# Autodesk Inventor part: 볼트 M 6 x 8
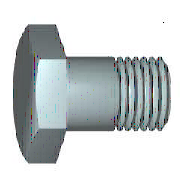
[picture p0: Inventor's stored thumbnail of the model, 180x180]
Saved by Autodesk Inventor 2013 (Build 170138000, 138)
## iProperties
Created: 2012-02
Part Number: 볼트 M 6 x 8
Material: 강철, 연강
Description: 6각 머리 볼트 및 6각 머리 나사
Document SubType Name: Modeling
Standard: KS B 1002
Designer: mduedu
Standards Organization: KS
Language: ko-KR
Size Designation: C  M 6 x 12
Categories: <MemberInstance><Categories><Category DisplayName="조임쇠" InternalName="e4da775c-781d-43d5-af7c-5136215cf5a6" Mnemonic="FSTN"><Category DisplayName="볼트" InternalN
Density: 1 g/cm^3
IsCustomPart: 1
Author: mduedu
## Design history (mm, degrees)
sketch "스케치1"
  geometry: L1 (0, 3)-(8, 3); L2 (8, 3)-(8, 0); L3 (8, 0)-(0, 0); L4 (-2.4, 0)-(14.4, 0) reference; L5 (0, -0.6)-(0, 3.6) reference; L6 (0, 3)-(0, 0)
  constraints: 8 end point, 3 point on line, 1 collinear
  dimensions: "d2" = 6 diameter of L1 L3 (= GD); "d59" = 8 distance between parallel lines of L2 L5 (= NLG)
revolve "본체" sketch "스케치1" stored, may be unused: angle "d12" = 90 deg
sketch "스케치2"
  geometry: L1 (0, 5.774)-(5, 2.887); L2 (5, 2.887)-(5, -2.887); L3 (5, -2.887)-(0, -5.774); L4 (0, -5.774)-(-5, -2.887); L5 (-5, -2.887)-(-5, 2.887); L6 (-5, 2.887)-(0, 5.774); L7 (-7, 0)-(7, 0) reference; L8 (0, 8.083)-(0, -8.083) reference; 2 further points
  constraints: 12 end point, 2 midpoint, 1 coincident, 1 vertical, 11 other
  dimensions: "d11" = 10 distance between parallel lines of L5 L2 (= SW)
extrude "머리" join sketch "스케치2" distance "d3" = 4 (= KOH); taper "d4" = 0 deg
revolve "모따기1" stored, may be unused: angle "d21" = 90 deg
workplane "Work Plane1"
body "Solid1"
feature "스레드" dims "d15" = 9 (= GEL), "d16" = 0
chamfer "모따기2" distance "d6" = 0.61345 (= -0.5 x SPD + 0.5 x GD); stored, may be unused: second distance "d7" = 0.61355 (computed from GUL), angle "d55" = 45 deg
sketch "스케치4"
  geometry: L1 (-3.423, 6)-(-4, 5); L2 (-1.1, 0)-(-0.234, 0); L3 (-4.753, 0)-(0.519, 0) reference; L4 (-4, 6)-(-3.423, 6); L5 (-4, 5)-(-4, 6); L6 (0, 7.2)-(0, -1.2) reference
  constraints: 8 end point, 1 parallel, 1 perpendicular, 1 point on line
  dimensions: "d65" = 10 diameter of L1.end L2 (= SW); "d67" = 30 deg angle of L1 L5 (= ANG1); "d68" = 12 diameter of L4 L2 (= 1.2 x SW); "d69" = 4 distance between parallel lines of L5 L6 (= KOH)
other parameters: "NLG" = 8 [user parameter; used in 1 equation term], "GD" = 6 (= NND) [user parameter; used in 2 equation terms], "BDM" = 6 (= NND) [user parameter], "KOH" = 4 [user parameter; used in 2 equation terms], "GEL" = 9 [user parameter; used in 1 equation term], "SW" = 10 [user parameter; used in 5 equation terms], "SPD" = 4.7731 (= NND - 1.2269 x PTC) [user parameter; used in 1 equation term], "SD2" = 6 (= NND) [user parameter], "SD" = 0 [user parameter], "ANG1" = 30 deg [user parameter; used in 1 equation term], "GAL" = 0.61345 (= 0.61345 x PTC) [user parameter], "GUL" = 0.61345 (= 0.61345 x PTC) [user parameter; used in 1 equation term], "d8" = 0, "RR" = 0.25 [user parameter], "d58" = 0, "RR1" = 0.1 [user parameter], "GD1" = 4.7731 (= THREADDIA - 1.2269 x PTC) [user parameter], "THREADDIA" = 6 [user parameter; used in 1 equation term], "TOA" = 30 deg [user parameter], "PTC" = 1 [user parameter; used in 5 equation terms], "NND" = 6 [user parameter; used in 4 equation terms], "E0" = 11.55 (= 1.155 x SW) [user parameter]
